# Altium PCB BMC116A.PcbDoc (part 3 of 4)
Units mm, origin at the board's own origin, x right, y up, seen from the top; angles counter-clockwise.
Board outline 154.94 x 104.14 mm, 6 copper layers (Top Layer, Signal Layer 1, Signal Layer 2, Signal Layer 3, Signal Layer 4, Bottom Layer), stack 1.56 mm thick; 252 components, 114 nets, 652 pads, 2530 vias.
Unrouted connection lines stored in the file: 13.
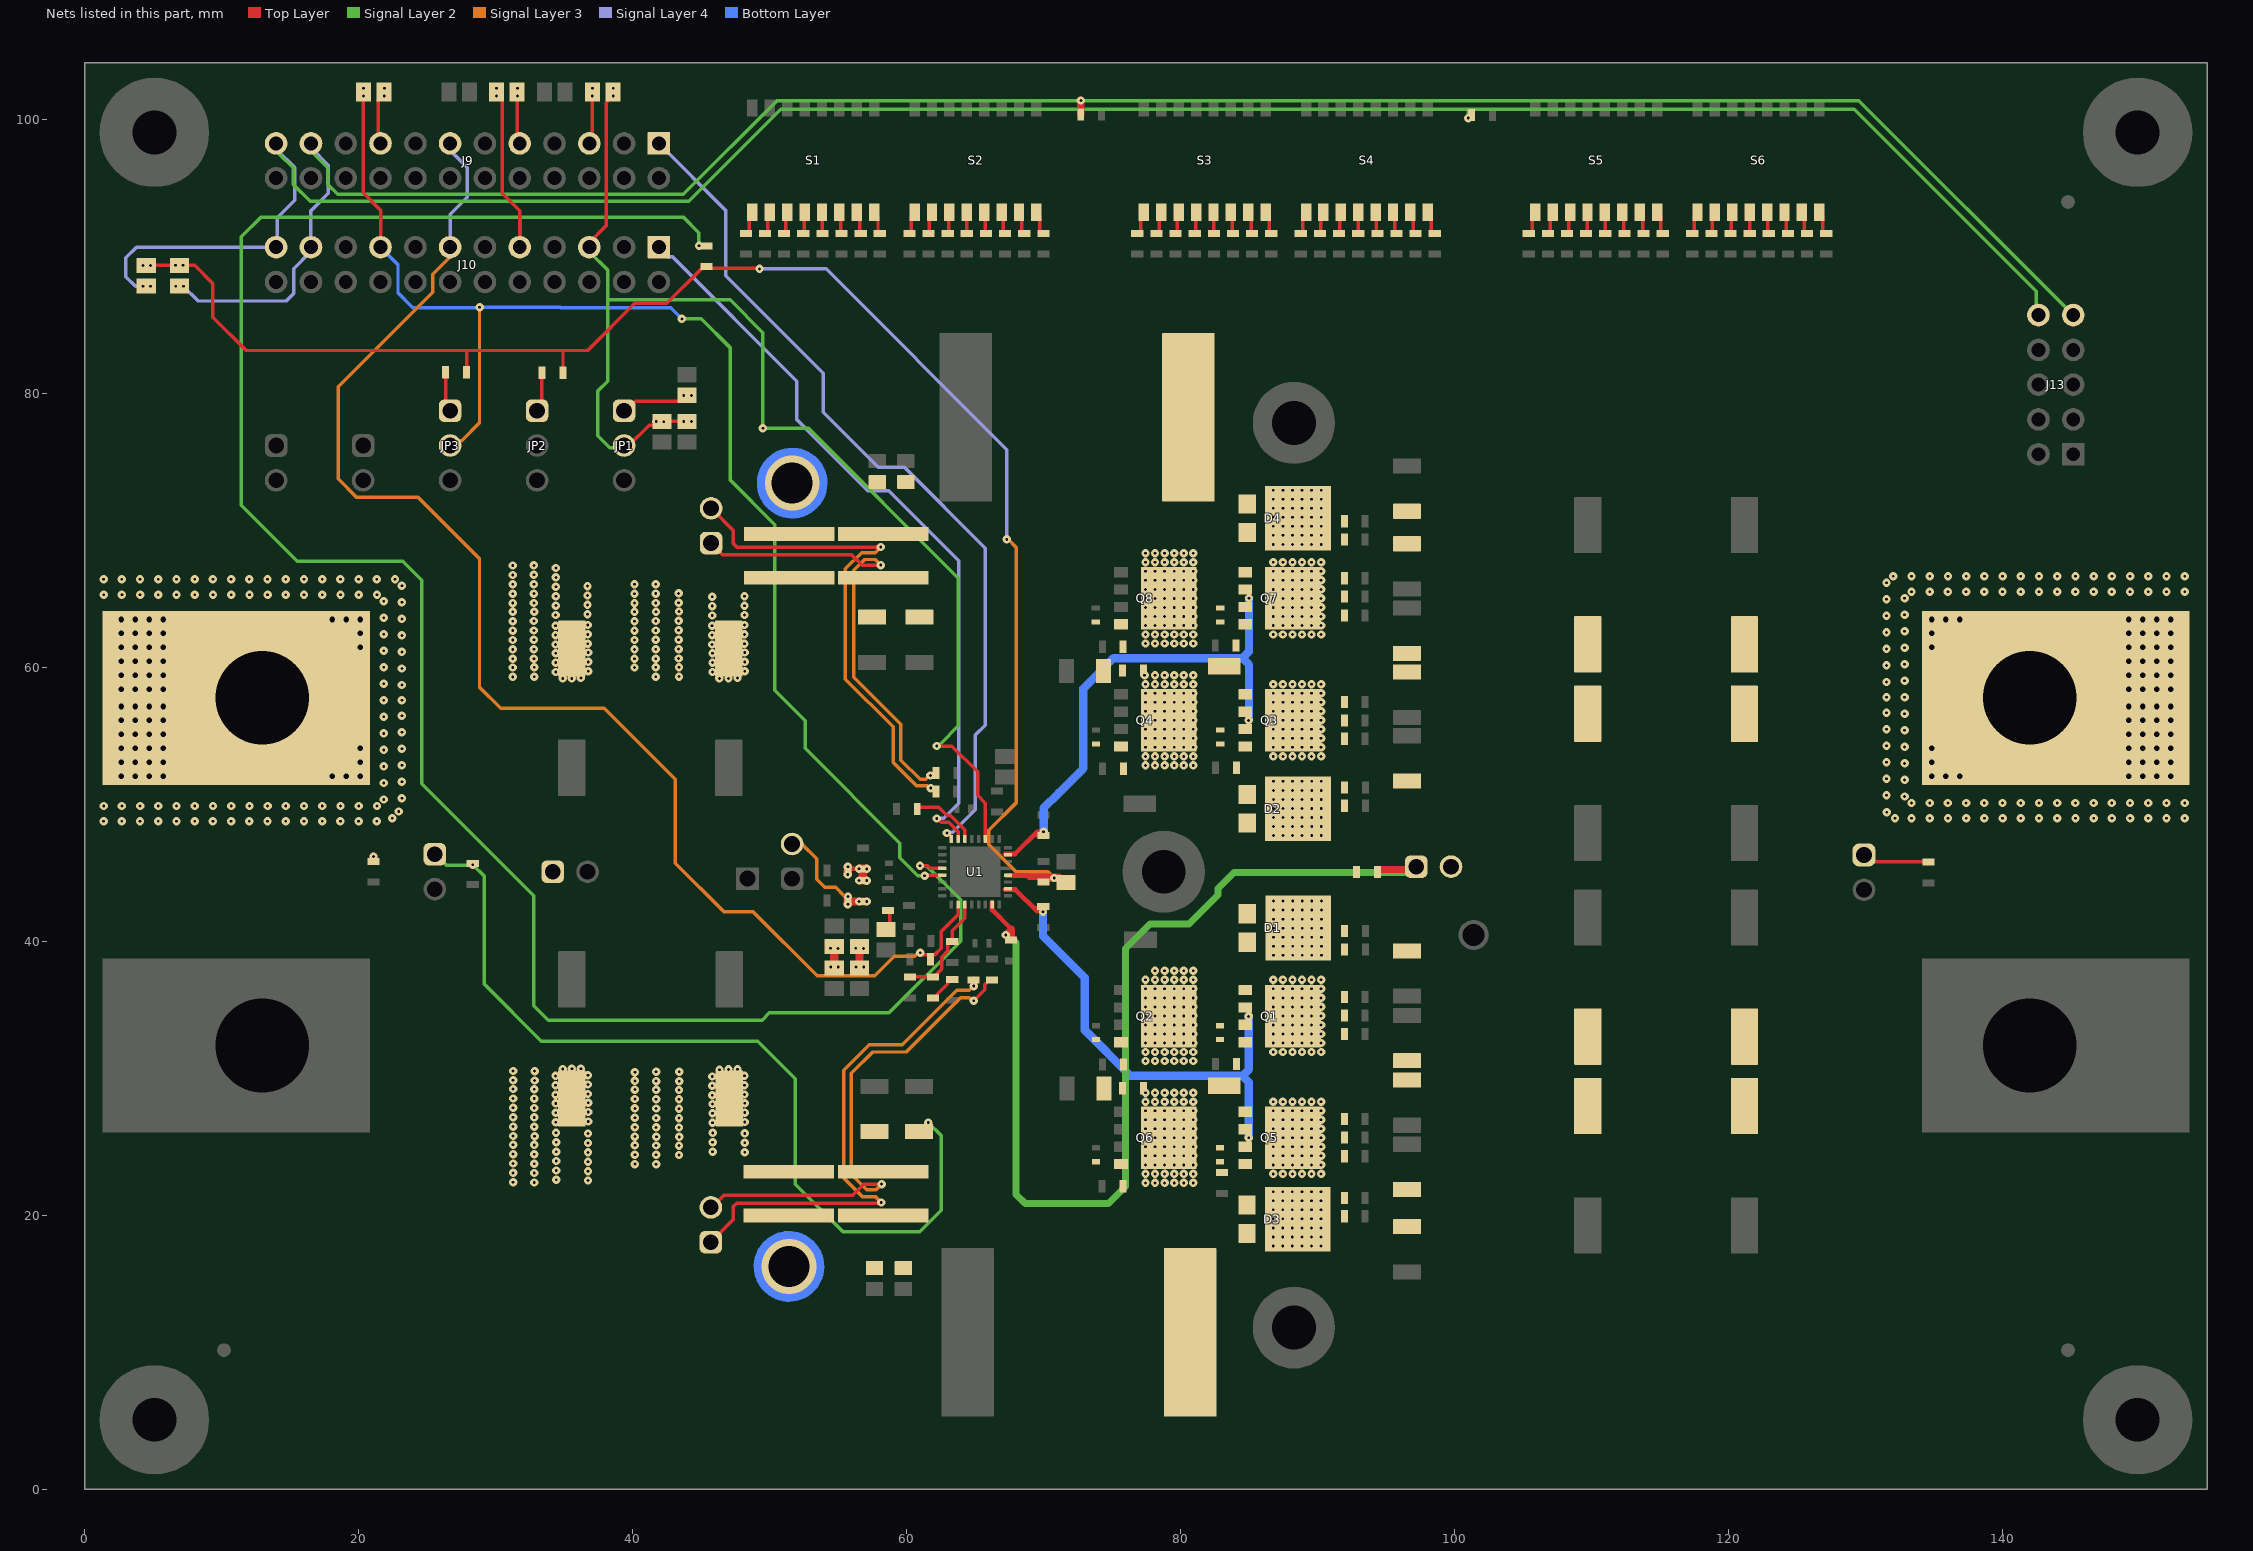
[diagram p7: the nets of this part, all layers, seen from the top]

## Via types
v1: diameter 0.61, hole 0.203, Top Layer to Bottom Layer, tented both sides, 2282 vias
v2: diameter 0.813, hole 0.406, Top Layer to Bottom Layer, 232 vias
v3: diameter 0.5, hole 0.2, Top Layer to Bottom Layer, tented both sides, 12 vias
v4: diameter 4, hole 3, Top Layer to Bottom Layer, 4 vias

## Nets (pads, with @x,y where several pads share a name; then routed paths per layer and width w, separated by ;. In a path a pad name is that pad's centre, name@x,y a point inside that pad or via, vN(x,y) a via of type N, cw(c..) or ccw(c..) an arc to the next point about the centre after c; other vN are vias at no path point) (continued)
MODE: J10.17 JP3.2 R100.1 U1.29 | length 100
  Top Layer w0.254: R100.1@20.338,101.47 20.338,94.639 21.59,93.387 J10.17@21.59,90.678 ; R100.1@20.338,101.72 R100.1@20.338,102 ; v1@61.268,44.688 v1@61.414,44.835 ; v1(61.308,44.796) 61.347,44.835 U1.29@62.599,44.835
  Top Layer w0.61: R100.1@20.348,101.724 v1(20.348,102.278)
  Signal Layer 2 w0.254: v1(43.591,85.443) 45.013,85.443 47.103,83.352 47.103,73.704 50.381,70.427 50.381,58.329 52.588,56.122 52.588,54.093 59.507,47.174 59.507,46.094 60.797,44.804 61.299,44.804 v1(61.308,44.796)
  Signal Layer 3 w0.254: JP3.2@26.67,76.2 27.048,76.2 27.408,76.56 27.508,76.56 28.815,77.867 28.815,86.294 v1(28.82,86.299)
  Bottom Layer w0.254: J10.17@21.59,90.678 22.864,89.404 22.864,87.349 23.949,86.264 28.785,86.264 v1(28.82,86.299) 34.699,86.299 34.734,86.264 42.77,86.264 v1(43.591,85.443)
  Bottom Layer w0.61: v1@20.348,101.724 v1(20.348,102.278)
  other v1: 20.344,101.72
MODE_SEC: J9.17 R100.2 | length 5.1
  Top Layer w0.254: J9.17@21.59,98.255 21.439,98.406 21.439,101.427 21.732,101.72 v1(21.868,101.72) ; R100.2@21.743,102 21.802,101.94 R100.2@21.87,101.873
  Top Layer w0.61: R100.2@21.872,101.724 v1(21.872,102.278)
  Bottom Layer w0.61: v1@21.872,101.724 v1(21.872,102.278)
NetC5_1: C5.1 C6.1 R95.2 U1.3 | length 7.9
  Top Layer w0.254: R95.2@60.361,37.391 60.377,37.407 61.779,37.407 61.795,37.423 61.986,37.423 62.552,37.989 62.552,38.849 63.006,39.303 63.006,39.856 63.133,39.983 C6.1@63.324,39.983 63.324,40.775 64.249,41.7 U1.3@64.249,42.685
NetC5_2: C5.2 R5.2 | length 2.2
  Top Layer w0.254: C5.2@61.785,36.006 C5.2@61.923,35.867 ; C5.2@62.029,35.933 62.18,35.933 62.241,35.994 62.241,36.145 63.007,36.912 63.007,37.102 63.134,37.229 R5.2@63.325,37.229
NetC9_2: C9.2 R29.2
NetC10_2: C10.2 R30.2
NetC16_1: C16.1 R8.1 | length 1.5
  Top Layer w0.254: C16.1@58.48,40.88 58.769,41.169 R8.1@58.769,42.269
NetC18_1: C18.1 JP5.2 R103.1 | length 9.2
  Top Layer w0.254: C18.1@55.709,42.99 55.782,42.917 v1(56.528,42.917) R103.1@56.805,42.917
  Top Layer w0.61: C18.1@55.699,42.918 R103.1@57.081,42.917 ; v1(55.709,42.713) C18.1@55.709,43.267
  Signal Layer 3 w0.254: JP5.2@51.97,47.112 52.343,47.112 53.421,46.033 53.421,44.547 54.006,43.962 54.811,43.962 55.463,43.31 v1@55.714,43.31
  other v1: 57.086,42.913 55.714,43.271
NetC19_1: C19.1 R103.2 R104.1 | length 4.5
  Top Layer w0.254: C19.1@55.704,45.166 C19.1@55.871,45.333 ; R104.1@56.527,45.194 56.775,45.194 56.802,45.221 56.802,44.444 R103.2@56.805,44.441
  Top Layer w0.305: C19.1@55.812,45.299 v1(56.527,45.299)
  Top Layer w0.61: v1(55.704,44.889) C19.1@55.704,45.443 ; v1(56.527,45.299) R104.1@57.08,45.299 ; v1(56.528,44.441) R103.2@57.081,44.441 ; R103.2@56.802,44.444 R104.1@56.803,45.299
  other v1: 57.086,44.437 57.084,45.295 55.709,45.447
NetJP1_1: JP1.1 R9.2 | length 5.1
  Top Layer w0.254: JP1.1@39.37,78.74 39.51,78.74 40.217,79.447 R9.2@43.663,79.447
  Top Layer w0.61: v1(43.732,79.856) R9.2@44.285,79.856
  other v1: 44.289,79.851
NetJP2_1: JP2.1 R89.1 | length 2.9
  Top Layer w0.254: JP2.1@33.02,78.74 33.346,79.066 33.346,81.469 R89.1@33.386,81.509
NetJP3_1: JP3.1 R90.1 | length 2.9
  Top Layer w0.254: R90.1@26.347,81.555 26.366,81.537 26.366,79.044 JP3.1@26.67,78.74
NetQ1_4: Q1.4 R21.1 R31.2
NetQ2_4: Q2.4 R22.2 R32.2
NetQ3_4: Q3.4 R23.2 R33.2
NetQ4_4: Q4.4 R24.1 R34.2
NetQ5_4: Q5.4 R25.1 R35.2
NetQ6_4: Q6.4 R26.2 R36.2
NetQ7_4: Q7.4 R27.2 R37.2
NetQ8_4: Q8.4 R28.1 R38.2
NetR41_1: R41.1 S1.1 | length 1.8
  Top Layer w0.254: R41.1@48.26,91.694 48.389,91.694 48.516,91.821 48.516,92.966 S1.1@48.768,93.218
NetR42_2: R42.2 S1.2 | length 1.7
  Top Layer w0.254: R42.2@49.657,91.694 49.721,91.694 49.847,91.821 49.847,93.027 S1.2@50.038,93.218
NetR43_1: R43.1 S1.3 | length 1.6
  Top Layer w0.254: R43.1@51.054,91.694 51.181,91.821 51.181,93.091 S1.3@51.308,93.218
NetR44_2: R44.2 S1.4 | length 1.6
  Top Layer w0.254: R44.2@52.451,91.694 52.517,91.76 52.517,93.157 S1.4@52.578,93.218
NetR45_1: R45.1 S1.5 | length 1.5
  Top Layer w0.254: R45.1@53.848,91.694 S1.5@53.848,93.218
NetR46_2: R46.2 S1.6 | length 1.6
  Top Layer w0.254: S1.6@55.118,93.218 55.182,93.154 55.182,91.757 R46.2@55.245,91.694
NetR47_2: R47.2 S1.7 | length 1.6
  Top Layer w0.254: S1.7@56.388,93.218 56.579,93.027 56.579,91.821 56.642,91.758 R47.2@56.642,91.694
NetR48_2: R48.2 S1.8 | length 1.7
  Top Layer w0.254: S1.8@57.658,93.218 57.906,92.97 57.906,91.821 58.033,91.694 R48.2@58.039,91.694
NetR49_2: R49.2 S2.1 | length 1.7
  Top Layer w0.254: R49.2@60.198,91.694 60.204,91.694 60.331,91.821 60.331,92.97 S2.1@60.579,93.218
NetR50_2: R50.2 S2.2 | length 1.6
  Top Layer w0.254: R50.2@61.595,91.694 61.595,91.758 61.658,91.821 61.658,93.027 S2.2@61.849,93.218
NetR51_2: R51.2 S2.3 | length 1.6
  Top Layer w0.254: R51.2@62.992,91.694 63.055,91.757 63.055,93.154 S2.3@63.119,93.218
NetR52_1: R52.1 S2.4 | length 1.5
  Top Layer w0.254: R52.1@64.389,91.694 S2.4@64.389,93.218
NetR53_2: R53.2 S2.5 | length 1.6
  Top Layer w0.254: S2.5@65.659,93.218 65.72,93.157 65.72,91.76 R53.2@65.786,91.694
NetR54_2: R54.2 S2.6 | length 1.6
  Top Layer w0.254: S2.6@66.929,93.218 67.056,93.091 67.056,91.821 R54.2@67.183,91.694
NetR55_2: R55.2 S2.7 | length 1.7
  Top Layer w0.254: S2.7@68.199,93.218 68.389,93.027 68.389,91.821 68.516,91.694 R55.2@68.58,91.694
NetR56_1: R56.1 S2.8 | length 1.8
  Top Layer w0.254: S2.8@69.469,93.218 69.721,92.966 69.721,91.821 69.848,91.694 R56.1@69.977,91.694
NetR57_1: R57.1 S3.1 | length 1.8
  Top Layer w0.254: R57.1@76.835,91.694 76.964,91.694 77.091,91.821 77.091,92.966 S3.1@77.343,93.218
NetR58_2: R58.2 S3.2 | length 1.7
  Top Layer w0.254: R58.2@78.232,91.694 78.295,91.694 78.422,91.821 78.422,93.027 S3.2@78.613,93.218
NetR59_1: R59.1 S3.3 | length 1.6
  Top Layer w0.254: R59.1@79.629,91.694 79.756,91.821 79.756,93.091 S3.3@79.883,93.218
NetR60_2: R60.2 S3.4 | length 1.6
  Top Layer w0.254: R60.2@81.026,91.694 81.092,91.76 81.092,93.157 S3.4@81.153,93.218
NetR61_1: R61.1 S3.5 | length 1.5
  Top Layer w0.254: R61.1@82.423,91.694 S3.5@82.423,93.218
NetR62_2: R62.2 S3.6 | length 1.6
  Top Layer w0.254: S3.6@83.693,93.218 83.757,93.154 83.757,91.757 R62.2@83.82,91.694
NetR63_2: R63.2 S3.7 | length 1.6
  Top Layer w0.254: S3.7@84.963,93.218 85.154,93.027 85.154,91.821 85.217,91.758 R63.2@85.217,91.694
NetR64_2: R64.2 S3.8 | length 1.7
  Top Layer w0.254: S3.8@86.233,93.218 86.481,92.97 86.481,91.821 86.608,91.694 R64.2@86.614,91.694
NetR65_2: R65.2 S4.1 | length 1.7
  Top Layer w0.254: R65.2@88.773,91.694 88.779,91.694 88.906,91.821 88.906,92.97 S4.1@89.154,93.218
NetR66_2: R66.2 S4.2 | length 1.6
  Top Layer w0.254: R66.2@90.17,91.694 90.17,91.758 90.233,91.821 90.233,93.027 S4.2@90.424,93.218
NetR67_2: R67.2 S4.3 | length 1.6
  Top Layer w0.254: R67.2@91.567,91.694 91.63,91.757 91.63,93.154 S4.3@91.694,93.218
NetR68_1: R68.1 S4.4 | length 1.5
  Top Layer w0.254: R68.1@92.964,91.694 S4.4@92.964,93.218
NetR69_2: R69.2 S4.5 | length 1.6
  Top Layer w0.254: S4.5@94.234,93.218 94.295,93.157 94.295,91.76 R69.2@94.361,91.694
NetR70_2: R70.2 S4.6 | length 1.6
  Top Layer w0.254: S4.6@95.504,93.218 95.631,93.091 95.631,91.821 R70.2@95.758,91.694
NetR71_2: R71.2 S4.7 | length 1.7
  Top Layer w0.254: S4.7@96.774,93.218 96.965,93.027 96.965,91.821 97.091,91.694 R71.2@97.155,91.694
NetR72_1: R72.1 S4.8 | length 1.8
  Top Layer w0.254: S4.8@98.044,93.218 98.296,92.966 98.296,91.821 98.423,91.694 R72.1@98.552,91.694
NetR73_1: R73.1 S5.1 | length 1.8
  Top Layer w0.254: R73.1@105.41,91.694 105.539,91.694 105.666,91.821 105.666,92.966 S5.1@105.918,93.218
NetR74_2: R74.2 S5.2 | length 1.7
  Top Layer w0.254: R74.2@106.807,91.694 106.87,91.694 106.998,91.821 106.998,93.027 S5.2@107.188,93.218
NetR75_1: R75.1 S5.3 | length 1.6
  Top Layer w0.254: R75.1@108.204,91.694 108.331,91.821 108.331,93.091 S5.3@108.458,93.218
NetR76_2: R76.2 S5.4 | length 1.6
  Top Layer w0.254: R76.2@109.601,91.694 109.667,91.76 109.667,93.157 S5.4@109.728,93.218
NetR77_1: R77.1 S5.5 | length 1.5
  Top Layer w0.254: R77.1@110.998,91.694 S5.5@110.998,93.218
NetR78_2: R78.2 S5.6 | length 1.6
  Top Layer w0.254: S5.6@112.268,93.218 112.332,93.154 112.332,91.757 R78.2@112.395,91.694
NetR79_2: R79.2 S5.7 | length 1.6
  Top Layer w0.254: S5.7@113.538,93.218 113.729,93.027 113.729,91.821 113.792,91.758 R79.2@113.792,91.694
NetR80_2: R80.2 S5.8 | length 1.7
  Top Layer w0.254: S5.8@114.808,93.218 115.056,92.97 115.056,91.821 115.183,91.694 R80.2@115.189,91.694
NetR81_2: R81.2 S6.1 | length 1.7
  Top Layer w0.254: R81.2@117.348,91.714 117.354,91.714 117.481,91.841 117.481,92.99 S6.1@117.729,93.238
NetR82_2: R82.2 S6.2 | length 1.6
  Top Layer w0.254: R82.2@118.745,91.714 118.745,91.778 118.808,91.841 118.808,93.047 S6.2@118.999,93.238
NetR83_2: R83.2 S6.3 | length 1.6
  Top Layer w0.254: R83.2@120.142,91.714 120.205,91.777 120.205,93.174 S6.3@120.269,93.238
NetR84_1: R84.1 S6.4 | length 1.5
  Top Layer w0.254: R84.1@121.539,91.714 S6.4@121.539,93.238
NetR85_2: R85.2 S6.5 | length 1.6
  Top Layer w0.254: S6.5@122.809,93.238 122.87,93.177 122.87,91.78 R85.2@122.936,91.714
NetR86_2: R86.2 S6.6 | length 1.6
  Top Layer w0.254: S6.6@124.079,93.238 124.206,93.111 124.206,91.841 R86.2@124.333,91.714
NetR87_2: R87.2 S6.7 | length 1.7
  Top Layer w0.254: S6.7@125.349,93.238 125.54,93.048 125.54,91.841 125.667,91.714 R87.2@125.73,91.714
NetR88_1: R88.1 S6.8 | length 1.8
  Top Layer w0.254: S6.8@126.619,93.238 126.871,92.986 126.871,91.841 126.998,91.714 R88.1@127.127,91.714
NetR91_2: R91.2 R93.1 | length 2
  Top Layer w0.61: v1(56.283,39.495) R93.1@56.836,39.495 ; v1(56.302,38.133) R91.2@56.856,38.133 ; R91.2@56.56,38.521 R93.1@56.56,39.436
  other v1: 56.86,38.129 56.84,39.49
NetR92_2: R92.2 R94.1 | length 2
  Top Layer w0.61: v1(54.431,39.495) R94.1@54.985,39.495 ; v1(54.451,38.133) R92.2@55.004,38.133 ; R92.2@54.722,38.503 R94.1@54.722,39.418
  other v1: 55.009,38.129 54.989,39.49
PGOOD: J10.9 R19.2 R98.1 U1.28 | length 163.7
  Top Layer w0.254: v1(30.055,101.72) R98.1@30.06,101.724 ; R98.1@30.062,101.953 R98.1@30.062,102 ; R98.1@30.175,101.84 30.472,101.543 30.472,100.384 30.472,94.617 31.75,93.339 J10.9@31.75,90.678 ; v1(44.834,90.782) 44.836,90.78 45.386,90.78 R19.2@45.388,90.777 ; v1@61.003,45.531 61.521,45.531 61.717,45.335 U1.28@62.599,45.335
  Top Layer w0.61: R98.1@30.06,101.724 v1(30.06,102.278)
  Signal Layer 2 w0.254: J10.9@31.75,90.678 31.75,92.86 ; v1(44.834,90.782) 44.834,91.734 43.708,92.86 33.239,92.86 12.86,92.86 11.427,91.427 11.427,71.841 15.518,67.75 23.215,67.75 24.609,66.355 24.609,51.509 32.787,43.331 32.787,35.297 33.834,34.25 49.442,34.25 49.97,34.779 58.708,34.779 63.938,40.009 63.938,40.452 63.938,43.038 61.448,45.529 v1(60.974,45.529)
  Signal Layer 3 w0.254: J10.9@31.75,90.305 J10.9@31.75,90.678
  Bottom Layer w0.61: v1@30.06,101.724 v1(30.06,102.278)
PGOOD_SEC: J9.9 R98.2 | length 4.6
  Top Layer w0.254: v1(31.579,101.72) 31.579,98.426 J9.9@31.75,98.255
  Top Layer w0.61: R98.2@31.584,101.724 v1(31.584,102.278)
  Bottom Layer w0.61: v1@31.584,101.724 v1(31.584,102.278)
RS1: J11.1 R1.1 R3.1 R11.2 R12.2 R16.2 | length 53.1
  Top Layer w0.254: J11.1@45.702,18.045 47.323,19.666 47.323,20.616 47.58,20.872 v1@58.084,20.872 ; R16.2@64.888,37.189 R16.2@64.901,37.176
  Top Layer w0.508: v1(64.901,36.737) R16.2@64.901,37.176
  Signal Layer 3 w0.254: v1(58.138,20.942) 57.737,21.343 56.8,21.343 55.413,22.73 55.413,30.592 57.264,32.443 59.667,32.443 63.664,36.44 64.574,36.44 64.871,36.737 v1(64.901,36.737)
  Bottom Layer w0.254: v4(51.409,16.272) 53.132,16.272 53.456,15.948
  Bottom Layer w1.016: 53.456,15.948 cw(c51.409,16.272) 53.463,15.995
RS2: J12.2 R2.2 R4.2 R13.1 R14.1 R18.2 | length 53.4
  Top Layer w0.254: J12.2@45.72,71.616 47.341,69.995 47.341,69.045 47.598,68.789 v1@58.102,68.789 ; v1(61.757,51.19) 61.999,51.19 62.126,51.063 R18.2@62.126,50.947
  Signal Layer 3 w0.254: v1(58.102,68.787) 57.693,68.377 56.71,68.377 55.527,67.194 55.527,59.144 59.012,55.658 59.012,53.061 60.695,51.379 61.472,51.379 61.643,51.207 v1@61.757,51.207
  Bottom Layer w0.254: v4@50.368,73.457 v4(51.638,73.457) 51.915,73.18 53.692,73.18
  Bottom Layer w1.016: 53.685,73.133 cw(c51.638,73.457) 53.692,73.18
RT: R6.2 U1.22 | length 4.6
  Top Layer w0.254: R6.2@60.984,49.793 62.346,49.793 62.926,49.213 63.179,49.213 64.249,48.143 U1.22@64.249,47.485
SCL: J9.21 J10.21 J13.9 R39.1 R102.1 | length 163.9
  Top Layer w0.559: R39.1@72.706,100.358 v1@72.706,101.382
  Top Layer w0.61: v1(6.643,87.827) R102.1@7.197,87.827
  Signal Layer 2 w0.254: J9.21@16.51,98.255 16.777,97.988 16.777,97.439 17.75,96.466 17.75,95.258 18.471,94.537 43.684,94.537 50.53,101.382 v1(72.719,101.382) 129.504,101.382 J13.9@145.161,85.725
  Signal Layer 4 w0.254: v1(7.201,87.822) 8.273,86.75 14.7,86.75 15.249,87.299 15.249,89.115 16.51,90.377 J10.21@16.51,90.678 16.51,93.336 17.784,94.61 17.784,96.674 16.51,97.949 J9.21@16.51,98.255
  Bottom Layer w0.61: v1(6.643,87.827) v1@7.197,87.827
SDA: J9.23 J10.23 J13.10 R40.1 R101.1 | length 166.7
  Top Layer w0.559: v1(100.99,100.102) R40.1@101.173,100.286
  Top Layer w0.61: v1(4.248,87.824) R101.1@4.802,87.824
  Signal Layer 2 w0.254: J9.23@13.97,98.255 14.237,97.988 14.237,97.439 15.21,96.466 15.21,95.258 16.445,94.023 44.081,94.023 50.812,100.754 72.453,100.754 72.457,100.75 100.99,100.75 ; v1(100.99,100.102) 100.99,100.75 ; J13.10@142.471,85.734 142.471,87.465 129.185,100.75 100.99,100.75
  Signal Layer 4 w0.254: v1(4.248,87.824) 3.702,87.824 3,88.526 3,89.901 3.777,90.678 J10.23@13.97,90.678 ; v1@4.253,87.82 v1(4.806,87.82) ; J10.23@14.059,90.448 14.059,92.84 15.332,94.112 15.332,96.496 14.059,97.769 J9.23@14.059,98.025
  Bottom Layer w0.61: v1(4.248,87.824) v1@4.802,87.824
SS: C8.1 J9.13 J10.13 U1.2 | length 101.5
  Top Layer w0.254: v1(60.987,39.169) 61.083,39.169 61.242,39.01 61.625,39.01 61.752,38.883 C8.1@61.752,38.693 ; C8.1@61.879,39.01 62.031,39.01 62.52,39.499 62.52,40.721 63.749,41.95 U1.2@63.749,42.512
  Signal Layer 3 w0.254: J10.13@27.015,90.316 25.396,88.697 25.396,87.389 18.504,80.497 18.504,73.764 19.833,72.434 24.323,72.434 28.815,67.943 28.815,58.551 30.353,57.013 37.914,57.013 43.102,51.825 43.102,45.719 46.64,42.18 48.776,42.18 53.472,37.484 57.661,37.484 59.079,38.903 60.572,38.903 v1@61.022,39.352
  Signal Layer 4 w0.254: J10.13@26.67,90.678 26.67,93.069 27.927,94.327 27.927,96.491 26.937,97.482 26.937,97.988 J9.13@26.67,98.255
SW1: C9.1 C13.1 D1.1 D1.2 D3.1 D3.2 L1.1 Q1.1 Q1.2 Q1.3 Q2.5 Q5.1 Q5.2 Q5.3 Q6.5 R31.1 R35.1 TP1.1 U1.10 | length 36.3
  Top Layer w0.254: 69.233,42.475 C13.1@69.995,42.475
  Top Layer w0.343: U1.10@67.175,43.784 67.938,43.784 69.517,42.205 69.919,42.205 v1(69.955,42.169)
  Bottom Layer w0.61: v1(69.955,42.169) 69.955,40.384 73.001,37.338 73.001,33.514 76.33,30.184 84.506,30.184 ; v1(84.977,25.672) 84.977,29.713 84.506,30.184 ; v1@84.977,34.562 84.977,30.655 84.506,30.184
  other v1: 77.432,22.37 78.131,22.37 78.829,22.37 79.528,22.37 80.226,22.37 80.925,22.37 77.432,23.028 78.131,23.028 78.829,23.028 79.528,23.028 80.226,23.028 80.925,23.028 77.432,23.687 78.131,23.687 78.829,23.687 79.528,23.687 80.226,23.687 80.925,23.687 77.432,24.346 78.131,24.346 78.829,24.346 79.528,24.346 80.226,24.346 80.925,24.346 77.432,25.004 78.131,25.004 78.829,25.004 79.528,25.004 80.226,25.004 80.925,25.004 77.432,25.663 78.131,25.663 78.829,25.663 79.528,25.663 80.226,25.663 80.925,25.663 77.432,26.321 78.131,26.321 78.829,26.321 79.528,26.321 80.226,26.321 80.925,26.321 77.432,26.98 78.131,26.98 78.829,26.98 79.528,26.98 80.226,26.98 80.925,26.98 77.432,27.638 78.131,27.638 78.829,27.638 79.528,27.638 80.226,27.638 80.925,27.638 77.432,28.297 78.131,28.297 78.829,28.297 79.528,28.297 80.226,28.297 80.925,28.297 77.432,28.955 78.131,28.955 78.829,28.955 79.528,28.955 80.226,28.955 80.925,28.955 77.433,31.268 78.132,31.268 78.83,31.268 79.529,31.268 80.227,31.268 80.926,31.268 77.433,31.927 78.132,31.927 78.83,31.927 79.529,31.927 80.227,31.927 80.926,31.927 77.433,32.585 78.132,32.585 78.83,32.585 79.529,32.585 80.227,32.585 80.926,32.585 77.433,33.244 78.132,33.244 78.83,33.244 79.529,33.244 80.227,33.244 80.926,33.244 77.433,33.902 78.132,33.902 78.83,33.902 79.529,33.902 80.227,33.902 80.926,33.902 84.963,34.525 77.433,34.561 78.132,34.561 78.83,34.561 79.529,34.561 80.227,34.561 80.926,34.561 77.433,35.219 78.132,35.219 78.83,35.219 79.529,35.219 80.227,35.219 80.926,35.219 77.433,35.878 78.132,35.878 78.83,35.878 79.529,35.878 80.227,35.878 80.926,35.878 77.433,36.536 78.132,36.536 78.83,36.536 79.529,36.536 80.227,36.536 80.926,36.536 77.433,37.195 78.132,37.195 78.83,37.195 79.529,37.195 80.227,37.195 80.926,37.195 78.132,37.853 78.83,37.853 79.529,37.853 80.227,37.853 80.926,37.853
SW2: C10.1 C14.2 D2.1 D2.2 D4.1 D4.2 L2.2 Q3.1 Q3.2 Q3.3 Q4.5 Q7.1 Q7.2 Q7.3 Q8.5 R33.1 R37.1 TP2.1 U1.15 | length 37.8
  Top Layer w0.254: 69.292,47.724 C14.2@70.054,47.724 ; v1(69.996,48.013) v1@70.092,48.013
  Top Layer w0.343: U1.15@67.175,46.386 67.907,46.386 69.529,48.007 69.991,48.007 v1(69.996,48.013)
  Bottom Layer w0.61: v1(69.996,48.013) 69.996,49.727 71.11,50.841 72.898,52.629 72.898,58.466 75.109,60.677 84.513,60.677 ; v1@84.985,56.164 84.985,60.206 84.513,60.677 ; v1(84.985,65.054) 84.985,61.148 84.513,60.677
  other v1: 77.432,52.85 78.131,52.85 78.829,52.85 79.528,52.85 80.226,52.85 80.925,52.85 77.432,53.508 78.131,53.508 78.829,53.508 79.528,53.508 80.226,53.508 80.925,53.508 77.432,54.167 78.131,54.167 78.829,54.167 79.528,54.167 80.226,54.167 80.925,54.167 77.432,54.825 78.131,54.825 78.829,54.825 79.528,54.825 80.226,54.825 80.925,54.825 77.432,55.484 78.131,55.484 78.829,55.484 79.528,55.484 80.226,55.484 80.925,55.484 77.432,56.143 78.131,56.143 78.829,56.143 79.528,56.143 80.226,56.143 80.925,56.143 84.963,56.134 77.432,56.801 78.131,56.801 78.829,56.801 79.528,56.801 80.226,56.801 80.925,56.801 77.432,57.46 78.131,57.46 78.829,57.46 79.528,57.46 80.226,57.46 80.925,57.46 77.432,58.118 78.131,58.118 78.829,58.118 79.528,58.118 80.226,58.118 80.925,58.118 77.432,58.777 78.131,58.777 78.829,58.777 79.528,58.777 80.226,58.777 80.925,58.777 77.37,59.435 78.131,59.435 78.829,59.435 79.528,59.435 80.226,59.435 80.925,59.435 77.433,61.748 78.132,61.748 78.83,61.748 79.529,61.748 80.227,61.748 80.926,61.748 77.433,62.407 78.132,62.407 78.83,62.407 79.529,62.407 80.227,62.407 80.926,62.407 77.433,63.065 78.132,63.065 78.83,63.065 79.529,63.065 80.227,63.065 80.926,63.065 77.433,63.724 78.132,63.724 78.83,63.724 79.529,63.724 80.227,63.724 80.926,63.724 77.433,64.382 78.132,64.382 78.83,64.382 79.529,64.382 80.227,64.382 80.926,64.382 77.433,65.041 78.132,65.041 78.83,65.041 79.529,65.041 80.227,65.041 80.926,65.041 77.433,65.699 78.132,65.699 78.83,65.699 79.529,65.699 80.227,65.699 80.926,65.699 77.433,66.358 78.132,66.358 78.83,66.358 79.529,66.358 80.227,66.358 80.926,66.358 77.433,67.016 78.132,67.016 78.83,67.016 79.529,67.016 80.227,67.016 80.926,67.016 77.433,67.675 78.132,67.675 78.83,67.675 79.529,67.675 80.227,67.675 80.926,67.675 77.433,68.333 78.132,68.333 78.83,68.333 79.529,68.333 80.227,68.333 80.926,68.333
SYNCIN: J9.1 U1.24 | length 63.3
  Top Layer w0.254: v1(62.936,47.914) 63.037,47.813 63.092,47.813 63.249,47.656 U1.24@63.249,47.485
  Signal Layer 4 w0.254: J9.1@41.91,98.255 46.805,93.36 46.805,88.583 53.903,81.485 53.903,78.618 57.919,74.603 59.843,74.603 65.742,68.703 65.742,55.79 65.017,55.065 65.017,50.841 65.017,49.616 63.357,47.955 62.977,47.955 v1(62.936,47.914)
SYNCOUT: J10.1 U1.23 | length 55.3
  Top Layer w0.254: v1(62.193,48.977) 62.235,48.977 62.52,48.692 63.057,48.692 63.747,48.002 63.747,47.487 U1.23@63.749,47.485
  Signal Layer 4 w0.254: J10.1@41.91,90.678 42.59,89.998 42.882,89.998 51.977,80.903 51.977,78.099 57.173,72.903 58.703,72.903 63.812,67.794 63.812,50.841 63.812,50.096 62.692,48.977 v1(62.193,48.977)
UVLO/EN: C20.1 J10.5 JP1.2 R10.1 R96.1 U1.19 | length 95.5
  Top Layer w0.254: J10.5@36.83,90.678 36.83,91.011 38.079,92.26 38.079,101.226 v1(38.574,101.72) ; JP1.2@39.37,76.2 39.703,76.2 41.195,77.692 41.554,77.692 41.719,77.857 C20.1@41.719,77.946 ; C20.1@41.822,77.843 C20.1@41.949,77.97 ; C20.1@42,77.97 42.271,77.97 R10.1@43.413,77.97 ; R10.1@43.566,77.97 R10.1@43.816,77.97 ; v1(62.192,54.261) 63.3,54.261 65.175,52.385 65.175,50.657 65.749,50.084 U1.19@65.749,47.485
  Top Layer w0.61: R96.1@38.578,101.724 v1(38.578,102.278) ; v1(41.713,77.946) C20.1@42.267,77.946 ; v1(43.732,77.956) R10.1@44.285,77.956
  Signal Layer 2 w0.254: J10.5@36.83,90.345 38.163,89.013 38.163,86.833 ; JP1.2@39.37,76.2 39.221,76.051 38.313,76.051 37.436,76.927 37.436,80.18 38.163,80.906 38.163,86.833 ; v1(49.5,77.454) 49.5,84.445 47.112,86.833 38.163,86.833 ; v1@49.5,77.477 52.825,77.477 63.777,66.525 63.777,55.74 62.475,54.438 62.466,54.438 62.275,54.247 v1@62.275,54.238
  Bottom Layer w0.61: v1@38.578,101.724 v1(38.578,102.278)
  other v1: 42.271,77.941 44.289,77.952
UVLO/EN_SEC: J9.5 R96.2 | length 4.7
  Top Layer w0.254: J9.5@36.83,98.255 37.05,98.475 v1(37.05,101.72)
  Top Layer w0.61: R96.2@37.054,101.724 v1(37.054,102.278)
  Bottom Layer w0.61: v1@37.054,101.724 v1(37.054,102.278)
VCC: C3.1 C4.1 R19.1 R89.2 R90.2 R101.2 R102.2 U1.12 | length 124.3
  Top Layer w0.254: R101.2@4.484,89.348 R101.2@4.802,89.348 ; R90.2@27.871,81.555 27.871,83.138 ; R89.2@34.91,81.509 34.91,83.138 ; v1(49.251,89.094) 49.219,89.126 45.855,89.126 45.515,89.126 R19.1@45.388,89.253 45.261,89.126 45.03,89.126 42.492,86.589 40.162,86.589 36.711,83.138 34.91,83.138 ; C3.1@70.156,44.48 70.176,44.461 C4.1@71.247,44.461 ; C4.1@71.25,44.448 71.489,44.448 C4.1@71.622,44.316 ; R101.2@4.802,89.348 R102.2@6.613,89.348 ; R101.2@4.802,89.348 R102.2@6.613,89.348 ; R102.2@6.613,89.348 R102.2@6.903,89.348 ; R102.2@6.613,89.348 R102.2@6.903,89.348 ; R102.2@6.903,89.348 7.171,89.348 8.029,89.348 9.352,88.026 9.352,85.566 11.78,83.138 27.871,83.138 ; 27.871,83.138 34.91,83.138
  Top Layer w0.343: U1.12@67.259,44.816 68.586,44.813 68.938,44.812
  Top Layer w0.457: 68.938,44.716 71.126,44.716 71.147,44.695 71.147,44.65 C4.1@71.247,44.55 ; C4.1@71.25,44.537 71.472,44.316 C4.1@71.622,44.316
  Top Layer w0.61: v1(4.248,89.348) R101.2@4.802,89.348 ; v1(6.613,89.366) R102.2@7.167,89.366
  Signal Layer 3 w0.254: v1(67.31,69.35) 67.407,69.35 68.015,68.741 68.015,50.142 65.987,48.114 65.987,47.076 67.98,45.083 70.314,45.083 v1(70.771,44.627)
  Signal Layer 4 w0.254: v1(49.251,89.094) 54.115,89.094 67.31,75.899 v1(67.31,69.35)
  Bottom Layer w0.61: v1(4.248,89.348) v1@4.802,89.348 ; v1(6.613,89.366) v1@7.167,89.366
  other v1: 4.806,89.344 7.171,89.362
VIN: C21.2 C22.2 C23.2 C24.2 C25.2 C26.2 C27.2 C28.2 C29.1 C30.1 J1.1 J5.1 J11.2 J12.1 JP4.1 R1.2 R2.1 R3.2 R4.1 R15.2 R17.2 T1.1 | length 137.4
  Top Layer w0.254: J11.2@45.72,20.537 46.662,21.479 55.077,21.479 56.062,21.479 56.862,22.28 v1(58.169,22.28) ; v1(58.112,67.471) 56.743,67.471 55.974,68.24 46.556,68.24 ; v1(61.732,52.116) 62.004,52.116 62.131,52.243 R17.2@62.131,52.3 ; v1(64.903,35.673) 65.705,36.475 65.705,36.852 65.916,37.062 66.043,37.189 R15.2@66.233,37.189 ; 46.556,68.24 J12.1@45.72,69.076 46.556,68.24
  Top Layer w0.584: C29.1@21.068,45.936 v1@21.068,46.19
  Signal Layer 2 w0.254: J5.1@25.578,46.355 25.62,46.355 26.399,45.576 28.297,45.576 v1(28.324,45.602) 29.178,44.749 29.178,36.862 33.318,32.722 49.135,32.722 51.873,29.985 51.873,22.283 55.351,18.805 60.945,18.805 62.516,20.377 62.516,25.83 v1(61.573,26.773)
  Signal Layer 3 w0.254: 56.143,67.085 56.937,67.879 57.703,67.879 v1(58.112,67.471) ; 56.143,67.108 56.143,59.275 59.577,55.84 59.577,53.237 60.982,51.833 61.406,51.833 61.689,52.116 v1(61.732,52.116) ; v1(58.169,22.28) 57.756,21.867 57.086,21.867 55.961,22.992 55.961,30.364 57.523,31.927 59.958,31.927 63.928,35.897 64.582,35.897 64.807,35.673 v1(64.903,35.673)
  other v1: 31.27,22.415 32.815,22.403 36.731,22.542 34.421,22.593 31.27,23.101 32.815,23.089 36.731,23.228 34.421,23.279 41.705,23.732 40.16,23.744 31.27,23.787 32.815,23.775 36.731,23.914 34.421,23.965 41.705,24.418 43.377,24.406 40.16,24.43 31.27,24.473 32.815,24.461 36.731,24.6 48.184,24.614 34.421,24.651 45.831,24.648 41.705,25.104 43.377,25.092 40.16,25.116 31.27,25.159 32.815,25.147 36.731,25.286 48.184,25.3 34.421,25.336 45.831,25.333 41.729,25.739 43.401,25.727 40.16,25.751 31.27,25.794 32.839,25.782 36.731,25.971 48.184,25.986 34.399,26.025 45.841,26.022 41.705,26.425 43.377,26.413 40.16,26.437 31.27,26.479 32.815,26.467 45.822,26.762 34.388,26.805 48.186,26.814 36.751,26.857 41.705,27.11 43.377,27.098 40.16,27.122 31.27,27.165 32.815,27.153 45.822,27.448 34.388,27.491 48.186,27.5 36.751,27.543 41.705,27.796 43.377,27.784 40.16,27.808 31.27,27.851 32.815,27.839 45.822,28.134 34.388,28.177 48.186,28.186 36.751,28.228 41.705,28.482 43.377,28.47 40.16,28.494 31.27,28.537 32.815,28.525 45.798,28.769 34.363,28.812 48.161,28.821 36.727,28.863 41.705,29.168 43.377,29.156 40.16,29.18 31.27,29.223 32.815,29.211 45.798,29.455 34.363,29.497 48.161,29.506 36.727,29.549 41.705,29.803 43.401,29.791 40.16,29.815 31.27,29.858 32.839,29.846 45.798,30.14 34.363,30.183 48.161,30.192 36.727,30.235 40.16,30.45 41.705,30.489 43.401,30.477 31.27,30.543 32.839,30.531 46.331,30.635 46.995,30.658 47.652,30.66 34.896,30.678 35.56,30.701 36.217,30.703 21.074,46.196 1.374,48.765 2.704,48.765 4.033,48.765 5.363,48.765 6.693,48.765 8.022,48.765 9.352,48.765 10.682,48.765 12.011,48.765 13.341,48.765 14.671,48.765 16.001,48.765 17.33,48.765 18.66,48.765 19.99,48.765 21.319,48.765 22.446,48.983 22.922,49.482 1.381,49.887 2.71,49.887 4.04,49.887 5.37,49.887 6.7,49.887 8.029,49.887 9.359,49.887 10.689,49.887 12.018,49.887 13.348,49.887 14.678,49.887 16.007,49.887 17.337,49.887 18.667,49.887 19.997,49.887 21.326,49.887 21.826,50.362 23.149,50.446 21.826,51.568 23.149,51.653 21.826,52.774 23.149,52.859 21.826,53.98 23.149,54.065 21.826,55.187 23.149,55.271 21.826,56.393 23.149,56.477 21.826,57.599 23.149,57.599 23.149,58.72 21.826,58.805 34.894,59.201 35.556,59.198 46.328,59.201 46.991,59.198 36.214,59.226 47.649,59.226 31.242,59.309 32.811,59.321 41.677,59.321 43.373,59.333 34.384,59.669 45.819,59.669 36.747,59.721 48.182,59.721 23.149,59.927 31.242,59.995 32.811,60.007 40.132,59.995 41.677,60.007 21.826,60.011 43.373,60.019 34.384,60.355 45.819,60.355 36.747,60.407 48.182,60.407 31.242,60.63 32.787,60.642 40.132,60.63 41.677,60.642 43.348,60.654 34.384,61.041 45.819,61.041 36.747,61.092 48.182,61.092 23.149,61.133 21.826,61.217 31.242,61.316 32.787,61.328 40.132,61.316 41.677,61.328 43.348,61.339 34.36,61.676 45.794,61.676 36.723,61.727 48.158,61.727 31.242,62.001 32.787,62.013 40.132,62.001 41.677,62.013 43.348,62.025 23.149,62.339 34.36,62.361 45.794,62.361 36.723,62.413 48.158,62.413 21.826,62.423 31.242,62.687 32.787,62.699 40.132,62.687 41.677,62.699 43.348,62.711 34.36,63.047 45.794,63.047 36.723,63.099 48.158,63.099 31.242,63.373 32.787,63.385 40.132,63.373 41.677,63.385 43.348,63.397 23.149,63.545 21.826,63.629 45.813,63.787 34.371,63.828 48.156,63.824 36.703,63.881 31.242,64.059 32.811,64.071 40.132,64.059 41.701,64.071 43.373,64.083 45.803,64.476 34.393,64.516 48.156,64.51 36.703,64.567 31.242,64.694 32.787,64.706 40.132,64.694 41.677,64.706 43.348,64.718 23.149,64.751 21.826,64.835 45.803,65.162 34.393,65.202 48.156,65.195 36.703,65.253 1.381,65.311 2.71,65.311 4.04,65.311 5.37,65.311 6.7,65.311 8.029,65.311 9.359,65.311 10.689,65.311 12.018,65.311 13.348,65.311 14.678,65.311 16.007,65.311 17.337,65.311 18.667,65.311 19.997,65.311 21.326,65.311 31.242,65.38 32.787,65.392 40.132,65.38 41.677,65.392 43.348,65.403 34.393,65.888 36.703,65.938 23.149,65.957 31.242,66.065 32.787,66.077 40.132,66.065 41.677,66.077 1.374,66.433 2.704,66.433 4.033,66.433 5.363,66.433 6.693,66.433 8.022,66.433 9.352,66.433 10.682,66.433 12.011,66.433 13.341,66.433 14.671,66.433 16.001,66.433 17.33,66.433 18.66,66.433 19.99,66.433 21.319,66.433 22.649,66.433 34.393,66.573 31.242,66.751 32.787,66.763 34.393,67.259 31.242,67.437 32.787,67.449
  other v2: 2.667,52.07 3.683,52.07 4.699,52.07 5.715,52.07 18.066,52.07 19.082,52.07 20.098,52.07 2.667,53.086 3.683,53.086 4.699,53.086 5.715,53.086 20.098,53.086 2.667,54.102 3.683,54.102 4.699,54.102 5.715,54.102 20.098,54.102 2.667,55.118 3.683,55.118 4.699,55.118 5.715,55.118 2.667,56.134 3.683,56.134 4.699,56.134 5.715,56.134 2.667,57.15 3.683,57.15 4.699,57.15 5.715,57.15 2.667,58.42 3.683,58.42 4.699,58.42 5.715,58.42 2.667,59.436 3.683,59.436 4.699,59.436 5.715,59.436 2.667,60.452 3.683,60.452 4.699,60.452 5.715,60.452 2.667,61.468 3.683,61.468 4.699,61.468 5.715,61.468 20.098,61.468 2.667,62.484 3.683,62.484 4.699,62.484 5.715,62.484 20.098,62.484 2.667,63.5 3.683,63.5 4.699,63.5 5.715,63.5 18.066,63.5 19.082,63.5 20.098,63.5
VOUT: C31.2 C32.2 C33.2 C34.2 C35.2 C36.2 C37.2 C38.2 C39.2 C40.2 C41.1 C42.1 C43.1 C44.1 C45.1 C46.1 C47.1 C48.1 C49.1 C50.1 C51.1 C52.1 C53.1 C54.1 C55.1 C56.1 C57.1 C58.1 C59.1 C60.1 C61.2 C62.2 C63.2 C64.2 C65.2 C66.2 C67.2 C68.2 C69.1 D1.3 D2.3 D3.3 D4.3 J3.1 J6.1 JP6.2 Q1.5 Q3.5 Q5.5 Q7.5 R20.1 T3.1 | length 5.4
  Top Layer w0.254: J6.1@129.882,46.294 130.183,46.294 130.654,45.824 134.568,45.824 C69.1@134.6,45.792 ; J6.1@130.185,45.885 J6.1@130.654,45.885
  other v1: 86.757,17.77 87.455,17.77 88.154,17.77 88.852,17.77 89.551,17.77 90.249,17.77 86.757,18.429 87.455,18.429 88.154,18.429 88.852,18.429 89.551,18.429 90.249,18.429 86.757,19.087 87.455,19.087 88.154,19.087 88.852,19.087 89.551,19.087 90.249,19.087 86.757,19.746 87.455,19.746 88.154,19.746 88.852,19.746 89.551,19.746 90.249,19.746 86.757,20.404 87.455,20.404 88.154,20.404 88.852,20.404 89.551,20.404 90.249,20.404 86.757,21.063 87.455,21.063 88.154,21.063 88.852,21.063 89.551,21.063 90.249,21.063 86.757,21.721 87.455,21.721 88.154,21.721 88.852,21.721 89.551,21.721 90.249,21.721 86.763,23.028 87.461,23.028 88.16,23.028 88.858,23.028 89.557,23.028 90.255,23.028 86.763,23.687 87.461,23.687 88.16,23.687 88.858,23.687 89.557,23.687 90.255,23.687 86.763,24.346 87.461,24.346 88.16,24.346 88.858,24.346 89.557,24.346 90.255,24.346 86.763,25.004 87.461,25.004 88.16,25.004 88.858,25.004 89.557,25.004 90.255,25.004 86.763,25.663 87.461,25.663 88.16,25.663 88.858,25.663 89.557,25.663 90.255,25.663 86.763,26.321 87.461,26.321 88.16,26.321 88.858,26.321 89.557,26.321 90.255,26.321 86.763,26.98 87.461,26.98 88.16,26.98 88.858,26.98 89.557,26.98 90.255,26.98 86.763,27.638 87.461,27.638 88.16,27.638 88.858,27.638 89.557,27.638 90.255,27.638 86.763,28.297 87.461,28.297 88.16,28.297 88.858,28.297 89.557,28.297 90.255,28.297 86.763,31.927 87.461,31.927 88.16,31.927 88.858,31.927 89.557,31.927 90.255,31.927 86.763,32.585 87.461,32.585 88.16,32.585 88.858,32.585 89.557,32.585 90.255,32.585 86.763,33.244 87.461,33.244 88.16,33.244 88.858,33.244 89.557,33.244 90.255,33.244 86.763,33.902 87.461,33.902 88.16,33.902 88.858,33.902 89.557,33.902 90.255,33.902 86.763,34.561 87.461,34.561 88.16,34.561 88.858,34.561 89.557,34.561 90.255,34.561 86.763,35.219 87.461,35.219 88.16,35.219 88.858,35.219 89.557,35.219 90.255,35.219 86.763,35.878 87.461,35.878 88.16,35.878 88.858,35.878 89.557,35.878 90.255,35.878 86.763,36.536 87.461,36.536 88.16,36.536 88.858,36.536 89.557,36.536 90.255,36.536 86.763,37.195 87.461,37.195 88.16,37.195 88.858,37.195 89.557,37.195 90.255,37.195 86.782,38.99 87.481,38.99 88.179,38.99 88.878,38.99 89.576,38.99 90.275,38.99 86.782,39.649 87.481,39.649 88.179,39.649 88.878,39.649 89.576,39.649 90.275,39.649 86.782,40.307 87.481,40.307 88.179,40.307 88.878,40.307 89.576,40.307 90.275,40.307 86.782,40.966 87.481,40.966 88.179,40.966 88.878,40.966 89.576,40.966 90.275,40.966 86.782,41.624 87.481,41.624 88.179,41.624 88.878,41.624 89.576,41.624 90.275,41.624 86.782,42.283 87.481,42.283 88.179,42.283 88.878,42.283 89.576,42.283 90.275,42.283 86.782,42.941 87.481,42.941 88.179,42.941 88.878,42.941 89.576,42.941 90.275,42.941 86.772,47.734 87.471,47.734 88.169,47.734 88.868,47.734 89.566,47.734 90.265,47.734 86.772,48.392 87.471,48.392 88.169,48.392 88.868,48.392 89.566,48.392 90.265,48.392 132.144,48.987 133.357,48.986 134.687,48.986 136.016,48.986 137.346,48.986 138.676,48.986 140.005,48.986 141.335,48.986 142.665,48.986 143.994,48.986 145.324,48.986 146.654,48.986 147.984,48.986 149.313,48.986 150.643,48.986 151.973,48.986 153.302,48.986 86.772,49.051 87.471,49.051 88.169,49.051 88.868,49.051 89.566,49.051 90.265,49.051 131.539,49.428 86.772,49.709 87.471,49.709 88.169,49.709 88.868,49.709 89.566,49.709 90.265,49.709 133.35,50.108 134.68,50.108 136.009,50.108 137.339,50.108 138.669,50.108 139.998,50.108 141.328,50.108 142.658,50.108 143.988,50.108 145.317,50.108 146.647,50.108 147.977,50.108 149.306,50.108 150.636,50.108 151.966,50.108 153.295,50.108 86.772,50.368 87.471,50.368 88.169,50.368 88.868,50.368 89.566,50.368 90.265,50.368 132.85,50.583 131.527,50.668 86.772,51.026 87.471,51.026 88.169,51.026 88.868,51.026 89.566,51.026 90.265,51.026 86.772,51.685 87.471,51.685 88.169,51.685 88.868,51.685 89.566,51.685 90.265,51.685 132.85,51.789 131.527,51.874 132.85,52.995 131.527,53.08 86.763,53.508 87.461,53.508 88.16,53.508 88.858,53.508 89.557,53.508 90.255,53.508 86.763,54.167 87.461,54.167 88.16,54.167 88.858,54.167 89.557,54.167 90.255,54.167 132.85,54.201 131.527,54.286 86.763,54.825 87.461,54.825 88.16,54.825 88.858,54.825 89.557,54.825 90.255,54.825 132.85,55.408 86.763,55.484 87.461,55.484 88.16,55.484 88.858,55.484 89.557,55.484 90.255,55.484 131.527,55.492 86.763,56.143 87.461,56.143 88.16,56.143 88.858,56.143 89.557,56.143 90.255,56.143 132.85,56.614 131.527,56.698 86.763,56.801 87.461,56.801 88.16,56.801 88.858,56.801 89.557,56.801 90.255,56.801 86.763,57.46 87.461,57.46 88.16,57.46 88.858,57.46 89.557,57.46 90.255,57.46 131.527,57.82 132.85,57.82 86.763,58.118 87.461,58.118 88.16,58.118 88.858,58.118 89.557,58.118 90.255,58.118 86.763,58.777 87.461,58.777 88.16,58.777 88.858,58.777 89.557,58.777 90.255,58.777 131.527,58.942 132.85,59.026 131.527,60.148 132.85,60.232 131.527,61.354 132.85,61.438 86.763,62.407 87.461,62.407 88.16,62.407 88.858,62.407 89.557,62.407 90.255,62.407 131.527,62.56 132.85,62.644 86.763,63.065 87.461,63.065 88.16,63.065 88.858,63.065 89.557,63.065 90.255,63.065 86.763,63.724 87.461,63.724 88.16,63.724 88.858,63.724 89.557,63.724 90.255,63.724 131.527,63.766 132.85,63.85 86.763,64.382 87.461,64.382 88.16,64.382 88.858,64.382 89.557,64.382 90.255,64.382 131.527,64.972 86.763,65.041 87.461,65.041 88.16,65.041 88.858,65.041 89.557,65.041 90.255,65.041 132.85,65.056 133.35,65.532 134.68,65.532 136.009,65.532 137.339,65.532 138.669,65.532 139.998,65.532 141.328,65.532 142.658,65.532 143.988,65.532 145.317,65.532 146.647,65.532 147.977,65.532 149.306,65.532 150.636,65.532 151.966,65.532 153.295,65.532 86.763,65.699 87.461,65.699 88.16,65.699 88.858,65.699 89.557,65.699 90.255,65.699 131.527,66.178 86.763,66.358 87.461,66.358 88.16,66.358 88.858,66.358 89.557,66.358 90.255,66.358 132.027,66.654 133.357,66.654 134.687,66.654 136.016,66.654 137.346,66.654 138.676,66.654 140.005,66.654 141.335,66.654 142.665,66.654 143.994,66.654 145.324,66.654 146.654,66.654 147.984,66.654 149.313,66.654 150.643,66.654 151.973,66.654 153.302,66.654 86.763,67.016 87.461,67.016 88.16,67.016 88.858,67.016 89.557,67.016 90.255,67.016 86.763,67.675 87.461,67.675 88.16,67.675 88.858,67.675 89.557,67.675 90.255,67.675 86.767,68.984 87.465,68.984 88.164,68.984 88.862,68.984 89.561,68.984 90.259,68.984 86.767,69.643 87.465,69.643 88.164,69.643 88.862,69.643 89.561,69.643 90.259,69.643 86.767,70.301 87.465,70.301 88.164,70.301 88.862,70.301 89.561,70.301 90.259,70.301 86.767,70.96 87.465,70.96 88.164,70.96 88.862,70.96 89.561,70.96 90.259,70.96 86.767,71.618 87.465,71.618 88.164,71.618 88.862,71.618 89.561,71.618 90.259,71.618 86.767,72.277 87.465,72.277 88.164,72.277 88.862,72.277 89.561,72.277 90.259,72.277 86.767,72.935 87.465,72.935 88.164,72.935 88.862,72.935 89.561,72.935 90.259,72.935
  other v2: 134.842,52.07 135.858,52.07 136.874,52.07 149.225,52.07 150.241,52.07 151.257,52.07 152.273,52.07 134.842,53.086 149.225,53.086 150.241,53.086 151.257,53.086 152.273,53.086 134.842,54.102 149.225,54.102 150.241,54.102 151.257,54.102 152.273,54.102 149.225,55.118 150.241,55.118 151.257,55.118 152.273,55.118 149.225,56.134 150.241,56.134 151.257,56.134 152.273,56.134 149.225,57.15 150.241,57.15 151.257,57.15 152.273,57.15 149.225,58.42 150.241,58.42 151.257,58.42 152.273,58.42 149.225,59.436 150.241,59.436 151.257,59.436 152.273,59.436 149.225,60.452 150.241,60.452 151.257,60.452 152.273,60.452 134.842,61.468 149.225,61.468 150.241,61.468 151.257,61.468 152.273,61.468 134.842,62.484 149.225,62.484 150.241,62.484 151.257,62.484 152.273,62.484 134.842,63.5 135.858,63.5 136.874,63.5 149.225,63.5 150.241,63.5 151.257,63.5 152.273,63.5
VOUT_7: C15.1 JP6.1 R20.2 U1.7 | length 76.5
  Top Layer w0.254: 66.249,42.325 U1.7@66.249,42.685
  Top Layer w0.33: 66.241,42.301 67.581,40.961
  Top Layer w0.356: 66.241,42.301 U1.7@66.241,42.835
  Top Layer w0.508: v1@67.239,40.492 67.641,40.895 C15.1@67.64,40.1 ; R20.2@94.363,45.066 94.363,45.249 97.037,45.249 JP6.1@97.194,45.406
  Signal Layer 2 w0.508: v1(67.239,40.465) 67.258,40.445 67.471,40.445 67.987,39.929 67.987,21.535 68.656,20.866 74.732,20.866 75.969,22.104 75.969,39.468 77.769,41.268 80.6,41.268 82.718,43.386 82.718,43.864 83.881,45.026 97.061,45.026 JP6.1@97.108,45.073
pads on no net: FID1.1 FID2.1 FID3.1 H1.1 H2.1 H3.1 H4.1 H5.0 H6.0 H7.0 H8.0 J9.3 J10.3 J13.1 J13.2 J13.3 J13.4 J13.5 J13.7 J13.8 SH-JP1.0 SH-JP2.0 SH-JP3.0 SH-JP4.0 SH-JP5.0 SH-JP6.0

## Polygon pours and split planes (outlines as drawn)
GND on Top Layer "TOP_LAYER_GND_P005" (solid, pour order 5): 92.892,63.458 93.052,63.298 97.803,63.298 97.962,63.457 97.962,66.458 97.222,67.197 93.088,67.197 92.892,67.001
GND on Top Layer "TOP_LAYER_GND_P003" (solid, pour order 3): 92.892,27.42 93.052,27.58 97.803,27.58 97.962,27.421 97.962,24.55 97.093,23.681 93.088,23.681 92.892,23.878
NetQ5_4 on Top Layer "TOP_LAYER_NETQ5_4_P009" (solid, pour order 9): 85.492,23.51 85.493,24.149 82.506,24.149 82.506,22.957 82.583,22.879 83.371,22.879 84.861,22.879
NetQ6_4 on Top Layer "TOP_LAYER_NETQ6_4_P015" (solid, pour order 15): 76.451,21.999 76.453,24.14 73.466,24.14 73.466,23.259 73.91,22.815 74.479,22.815 74.809,22.485 74.809,21.711 74.838,21.682 76.134,21.682
NetQ3_4 on Top Layer "TOP_LAYER_NETQ3_4_P016" (solid, pour order 16): 85.518,52.479 85.521,54.62 82.534,54.62 82.534,53.739 82.896,53.376 83.466,53.376 83.8,53.042 83.8,52.249 83.886,52.162 85.202,52.162
GND on Top Layer "TOP_LAYER_GND_P055" (solid, pour order 55): 93.814,39.02 93.573,38.778 93.091,38.778 92.885,38.984 92.885,41.236 93.043,41.394 93.543,41.394 93.814,41.122
GND on Top Layer "TOP_LAYER_GND_P057" (solid, pour order 57): 93.814,51.64 93.573,51.881 93.091,51.881 92.885,51.675 92.885,49.423 93.043,49.266 93.543,49.266 93.814,49.537
GND on Top Layer "TOP_LAYER_GND_P067" (solid, pour order 67): 93.798,21.676 93.557,21.918 93.076,21.918 92.87,21.712 92.87,19.46 93.027,19.302 93.527,19.302 93.798,19.573
GND on Top Layer "TOP_LAYER_GND_P073" (solid, pour order 73): 93.798,68.937 93.557,68.696 93.076,68.696 92.87,68.902 92.87,71.154 93.027,71.311 93.527,71.311 93.798,71.04
NetQ1_4 on Top Layer "TOP_LAYER_NETQ1_4_P075" (solid, pour order 75): 85.531,30.985 85.534,33.031 82.546,33.031 82.546,32.149 82.78,31.915 83.258,31.915 83.741,31.432 83.741,30.714 83.832,30.623 85.169,30.623
NetQ7_4 on Top Layer "TOP_LAYER_NETQ7_4_P076" (solid, pour order 76): 85.531,61.49 85.534,63.536 82.546,63.536 82.546,62.654 82.78,62.42 83.258,62.42 83.741,61.937 83.741,61.219 83.832,61.128 85.169,61.128
GND on Top Layer "TOP_LAYER_GND_P077" (solid, pour order 77): 122.88,39.852 122.221,39.192 120.114,39.192 119.423,39.884 119.423,43.913 122.83,43.913 122.88,43.863
GND on Top Layer "TOP_LAYER_GND_P078" (solid, pour order 78): 111.45,39.852 110.791,39.192 108.684,39.192 107.993,39.884 107.993,43.913 111.4,43.913 111.45,43.863
GND on Top Layer "TOP_LAYER_GND_P079" (solid, pour order 79): 119.427,49.572 120.087,50.232 122.193,50.232 122.885,49.54 122.885,45.51 119.477,45.51 119.427,45.56
GND on Top Layer "TOP_LAYER_GND_P080" (solid, pour order 80): 108.006,49.81 108.665,50.47 110.772,50.47 111.463,49.778 111.463,45.749 108.056,45.749 108.006,45.799
GND on Top Layer "TOP_LAYER_GND_P084" (solid, pour order 84): 92.892,36.378 93.075,36.562 97.743,36.562 97.962,36.343 97.962,33.36 97.24,32.639 93.088,32.639 92.892,32.836
AGND on Top Layer "TOP_LAYER_AGND_P085" (solid, remove dead copper, pour order 85): 0.647,103.493 0.647,67.271 23.031,67.271 28.124,72.364 41.213,72.364 45.851,77.002 45.851,84.33 51.09,89.569 138.316,89.569 140.75,87.136 140.75,74.946 141.946,73.75 154.25,73.75 154.25,103.493
L2 on Top Layer "TOP_LAYER_L2_P088" (solid, remove dead copper, pour order 88): 55.702,75.206 56.346,74.563 62.4,74.568 62.4,72.107 67.472,72.107 71.514,76.038 71.514,79.396 66.416,84.494 59.908,84.494 55.702,80.288
L1 on Top Layer "TOP_LAYER_L1_P089" (solid, remove dead copper, pour order 89): 55.728,14.456 56.401,15.129 62.525,15.135 62.54,17.611 66.655,17.611 71.694,13.674 71.694,10.34 66.595,5.241 59.86,5.241 55.728,9.374
NetQ2_4 on Top Layer "TOP_LAYER_NETQ2_4_P093" (solid, pour order 93): 76.451,30.889 76.453,33.03 73.466,33.03 73.466,32.149 73.91,31.705 74.479,31.705 74.809,31.375 74.809,30.601 74.838,30.572 76.134,30.572
NetQ8_4 on Top Layer "TOP_LAYER_NETQ8_4_P094" (solid, pour order 94): 76.451,61.394 76.453,63.536 73.466,63.536 73.466,62.654 73.91,62.21 74.479,62.21 74.809,61.881 74.809,61.107 74.838,61.078 76.134,61.078
RS1 on Top Layer "Top Layer-RS^1" (solid, pour order 99): 48.063,20.497 56.704,20.497 56.704,21.301 61.957,21.301 61.957,15.805 54.413,15.805 52.391,13.783 50.571,13.783 48.064,16.29
RS2 on Top Layer "Top Layer-RS2" (solid, pour order 100): 48.105,69.215 56.642,69.215 56.642,68.434 61.982,68.434 61.982,73.405 61.43,73.957 54.405,73.957 52.416,75.946 50.597,75.946 48.109,73.459
NetC10_2 on Top Layer "TOP_LAYER_NETC10_2_P101" (solid, pour order 101): 73.839,60.622 75.096,60.622 75.51,60.207 76.014,60.207 76.014,59.318 76.017,59.315 75.508,59.315 75.067,58.874 73.839,58.874
NetC9_2 on Top Layer "TOP_LAYER_NETC9_2_P102" (solid, pour order 102): 73.839,30.116 75.096,30.116 75.51,29.702 76.014,29.702 76.014,28.813 76.017,28.81 75.508,28.81 75.067,28.368 73.839,28.368
NetQ4_4 on Top Layer "TOP_LAYER_NETQ4_4_P103" (solid, pour order 103): 76.451,52.479 76.453,54.62 73.466,54.62 73.466,53.739 73.91,53.295 74.479,53.295 74.809,52.965 74.809,52.191 74.838,52.162 76.134,52.162
SW1 on Top Layer "TOP_LAYER_SW1_P104" (solid, pour order 104): 85.547,21.26 85.547,42.718 85.427,42.837 82.475,42.837 76.998,37.359 76.996,17.662 74.791,14.915 74.791,8.963 78.519,5.235 82.84,5.235 83.351,5.745 83.351,16.456 84.258,17.364 85.547,17.364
